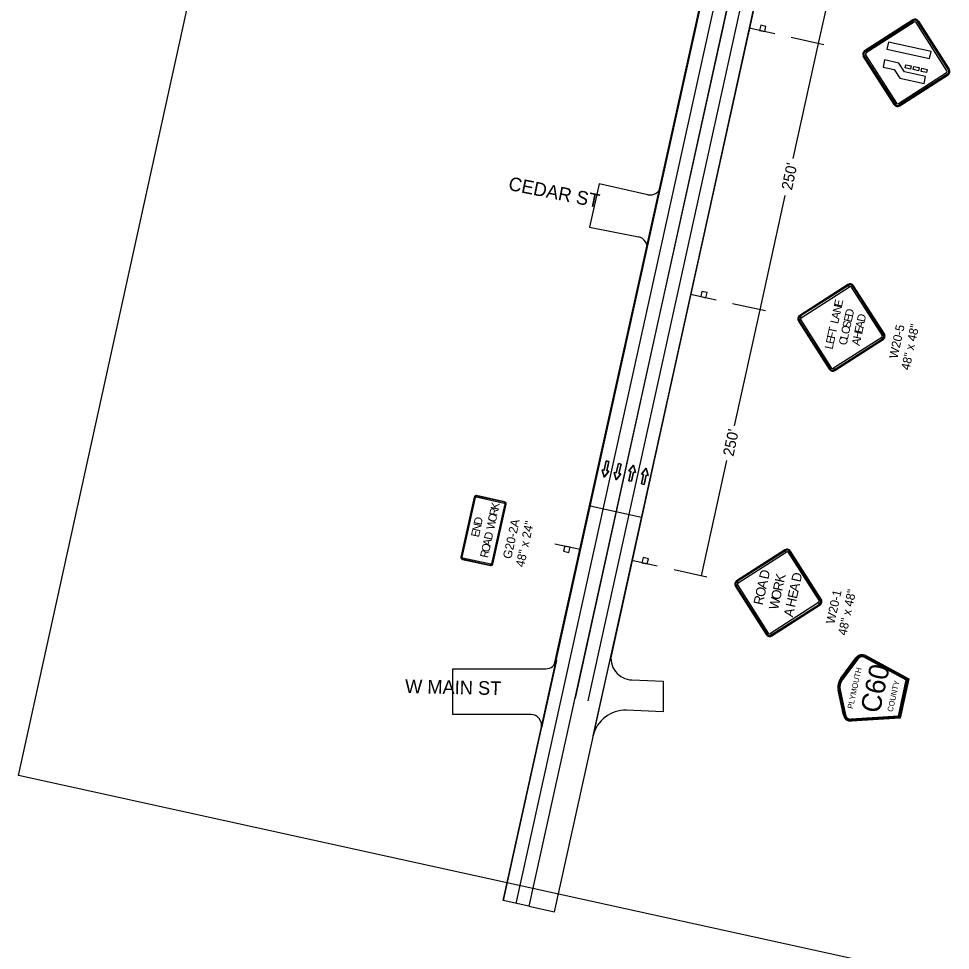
# Model space of a CAD drawing. Extents: x 14104283 to 14120882, y 8635219 to 8671666.
# Drawn here: x 14106925 to 14107780, y 8637146 to 8638001 of the extents above; entities that cross this region are included whole.
import ezdxf

# ---------------------------------------------------------------- set-up
doc = ezdxf.new("R2010")
doc.units = 0
for name, color, linetype in [('Cell', 7, 'Continuous'), ('Default', 7, 'Continuous'), ('dsnNonPlotable', 7, 'Continuous'), ('dsnPaintExistingBrokenLaneLineWhite', 7, 'Continuous'), ('dsnPaintExistingDoubleCenterYellow', 7, 'Continuous'), ('dsnPaintExistingEdgeLineRightWhite', 7, 'Continuous'), ('dsnStdLabel', 7, 'Continuous'), ('dsnTextOverlapOdd', 7, 'Continuous'), ('Sign', 7, 'Continuous')]:
    doc.layers.add(name, color=color, linetype=linetype)

msp = doc.modelspace()

# ---------------------------------------------------------------- linework, layer by layer
at = {"layer": 'Cell'}
for p, q in [((14107700.87, 8637971.42), (14107745.09, 8637999.71)), ((14107745.09, 8637999.71), (14107700.87, 8637971.42)), ((14107701.37, 8637970.63), (14107745.6, 8637998.92)), ((14107746.44, 8637997.61), (14107702.22, 8637969.31)), ((14107776.46, 8637953), (14107748.17, 8637997.23)), ((14107749.48, 8637998.07), (14107777.78, 8637953.84)), ((14107750.27, 8637998.57), (14107778.57, 8637954.35)), ((14107778.57, 8637954.35), (14107750.27, 8637998.57)), ((14107618.57, 8637986.78), (14107595.13, 8637991.93)), ((14107728.02, 8637922.01), (14107699.73, 8637966.24)), ((14107699.73, 8637966.24), (14107728.02, 8637922.01)), ((14107699.73, 8637966.24), (14107699.73, 8637966.24)), ((14107728.81, 8637922.52), (14107700.52, 8637966.74)), ((14107701.84, 8637967.58), (14107701.84, 8637967.59)), ((14107701.84, 8637967.58), (14107730.13, 8637923.36)), ((14107731.86, 8637922.98), (14107776.08, 8637951.28)), ((14107776.92, 8637949.96), (14107732.7, 8637921.67)), ((14107777.43, 8637949.17), (14107733.2, 8637920.88)), ((14107733.2, 8637920.88), (14107777.43, 8637949.17)), ((14107685.59, 8637756.92), (14107641.37, 8637728.63)), ((14107686.1, 8637756.13), (14107686.94, 8637754.82)), ((14107688.67, 8637754.44), (14107689.98, 8637755.28)), ((14107719.06, 8637711.56), (14107690.77, 8637755.78)), ((14107564.62, 8637742.67), (14107541.18, 8637747.82)), ((14107640.23, 8637723.45), (14107668.52, 8637679.22)), ((14107641.02, 8637723.95), (14107642.34, 8637724.8)), ((14107642.72, 8637726.52), (14107641.87, 8637727.84)), ((14107673.7, 8637678.09), (14107717.93, 8637706.38)), ((14107716.58, 8637708.49), (14107717.42, 8637707.17)), ((14107718.27, 8637711.05), (14107716.96, 8637710.21)), ((14107670.63, 8637680.57), (14107669.31, 8637679.73)), ((14107673.2, 8637678.88), (14107672.36, 8637680.19)), ((14107342.77, 8637561.94), (14107330.7, 8637507)), ((14107343.23, 8637561.84), (14107343.99, 8637561.68)), ((14107344.74, 8637562.15), (14107344.9, 8637562.92)), ((14107370.64, 8637557.74), (14107345, 8637563.37)), ((14107360, 8637500.57), (14107372.07, 8637555.51)), ((14107370.54, 8637557.28), (14107370.37, 8637556.52)), ((14107370.85, 8637555.78), (14107371.61, 8637555.61)), ((14107416.71, 8637519.21), (14107440.15, 8637514.06)), ((14107627.73, 8637513.57), (14107583.51, 8637485.28)), ((14107628.24, 8637512.78), (14107629.08, 8637511.46)), ((14107630.81, 8637511.09), (14107632.12, 8637511.93)), ((14107661.21, 8637468.21), (14107632.91, 8637512.43)), ((14107331.92, 8637506.74), (14107331.16, 8637506.9)), ((14107332.13, 8637504.77), (14107357.77, 8637499.14)), ((14107332.23, 8637505.23), (14107332.4, 8637505.99)), ((14107359.54, 8637500.67), (14107358.78, 8637500.84)), ((14107510.73, 8637498.55), (14107487.29, 8637503.7)), ((14107358.04, 8637500.36), (14107357.87, 8637499.6)), ((14107584.86, 8637483.17), (14107584.02, 8637484.49)), ((14107582.37, 8637480.1), (14107610.67, 8637435.87)), ((14107583.16, 8637480.6), (14107584.48, 8637481.44)), ((14107660.42, 8637467.7), (14107659.1, 8637466.86)), ((14107615.85, 8637434.73), (14107660.07, 8637463.03)), ((14107658.72, 8637465.13), (14107659.56, 8637463.82)), ((14107612.77, 8637437.22), (14107611.46, 8637436.38)), ((14107615.34, 8637435.53), (14107614.5, 8637436.84))]:
    msp.add_line(p, q, dxfattribs=at)
for points in [[(14107745.6, 8637998.92), (14107701.37, 8637970.63)], [(14107746.44, 8637997.61), (14107702.22, 8637969.31)], [(14107776.46, 8637953), (14107748.17, 8637997.23)], [(14107777.78, 8637953.84), (14107749.48, 8637998.07)], [(14107604.57, 8637989.94), (14107609.37, 8637988.89), (14107610.42, 8637993.68), (14107605.62, 8637994.74), (14107604.57, 8637989.94)], [(14107700.52, 8637966.74), (14107728.81, 8637922.52)], [(14107701.84, 8637967.59), (14107730.13, 8637923.36)], [(14107731.86, 8637922.98), (14107776.08, 8637951.28)], [(14107732.7, 8637921.67), (14107776.92, 8637949.96)], [(14107550.62, 8637745.83), (14107555.41, 8637744.78), (14107556.46, 8637749.57), (14107551.67, 8637750.63), (14107550.62, 8637745.83)], [(14107462.11, 8637586.65), (14107460.28, 8637587.05), (14107462, 8637580.28), (14107466.38, 8637585.72), (14107464.55, 8637586.12), (14107466.42, 8637594.67), (14107463.97, 8637595.2), (14107462.11, 8637586.65)], [(14107473.17, 8637584.22), (14107471.34, 8637584.62), (14107473.06, 8637577.85), (14107477.44, 8637583.29), (14107475.61, 8637583.69), (14107477.48, 8637592.24), (14107475.04, 8637592.77), (14107473.17, 8637584.22)], [(14107488.87, 8637584.97), (14107490.7, 8637584.57), (14107488.98, 8637591.35), (14107484.6, 8637585.91), (14107486.43, 8637585.51), (14107484.56, 8637576.96), (14107487.01, 8637576.43), (14107488.87, 8637584.97)], [(14107500.51, 8637582.16), (14107502.34, 8637581.76), (14107500.62, 8637588.53), (14107496.23, 8637583.09), (14107498.06, 8637582.69), (14107496.2, 8637574.14), (14107498.64, 8637573.61), (14107500.51, 8637582.16)], [(14107430.72, 8637516.05), (14107425.92, 8637517.1), (14107424.87, 8637512.3), (14107429.66, 8637511.25), (14107430.72, 8637516.05)], [(14107496.73, 8637501.71), (14107501.52, 8637500.66), (14107502.58, 8637505.45), (14107497.78, 8637506.51), (14107496.73, 8637501.71)]]:
    msp.add_lwpolyline(points, dxfattribs=at)
for points in [[(14107604.57, 8637989.94), (14107609.37, 8637988.89), (14107610.42, 8637993.68), (14107605.62, 8637994.74)], [(14107721.41, 8637972.77), (14107760.48, 8637964.18), (14107761.93, 8637970.78), (14107722.86, 8637979.36)], [(14107728.12, 8637954.01), (14107733.17, 8637946.12), (14107755.44, 8637941.23), (14107756.89, 8637947.82), (14107737.35, 8637952.11), (14107732.3, 8637960.01), (14107719.24, 8637962.88), (14107717.79, 8637956.28)], [(14107738.13, 8637955.65), (14107738.77, 8637958.58), (14107743.66, 8637957.51), (14107743.01, 8637954.58)], [(14107745.45, 8637954.04), (14107746.1, 8637956.97), (14107750.98, 8637955.9), (14107750.34, 8637952.97)], [(14107752.78, 8637952.44), (14107753.42, 8637955.37), (14107758.31, 8637954.29), (14107757.66, 8637951.36)], [(14107550.62, 8637745.83), (14107555.41, 8637744.78), (14107556.46, 8637749.57), (14107551.67, 8637750.63)], [(14107686.1, 8637756.13), (14107641.87, 8637727.84), (14107642.72, 8637726.52), (14107686.94, 8637754.82), (14107686.1, 8637756.13)], [(14107718.27, 8637711.05), (14107689.98, 8637755.28), (14107688.67, 8637754.44), (14107716.96, 8637710.21), (14107718.27, 8637711.05)], [(14107641.02, 8637723.95), (14107669.31, 8637679.73), (14107670.63, 8637680.57), (14107642.34, 8637724.8), (14107641.02, 8637723.95)], [(14107673.2, 8637678.88), (14107717.42, 8637707.17), (14107716.58, 8637708.49), (14107672.36, 8637680.19), (14107673.2, 8637678.88)], [(14107463.97, 8637595.2), (14107466.42, 8637594.67), (14107464.55, 8637586.12), (14107466.38, 8637585.72), (14107462, 8637580.28), (14107460.28, 8637587.05), (14107462.11, 8637586.65)], [(14107475.04, 8637592.77), (14107477.48, 8637592.24), (14107475.61, 8637583.69), (14107477.44, 8637583.29), (14107473.06, 8637577.85), (14107471.34, 8637584.62), (14107473.17, 8637584.22)], [(14107487.01, 8637576.43), (14107484.56, 8637576.96), (14107486.43, 8637585.51), (14107484.6, 8637585.91), (14107488.98, 8637591.35), (14107490.7, 8637584.57), (14107488.87, 8637584.97)], [(14107498.64, 8637573.61), (14107496.2, 8637574.14), (14107498.06, 8637582.69), (14107496.23, 8637583.09), (14107500.62, 8637588.53), (14107502.34, 8637581.76), (14107500.51, 8637582.16)], [(14107343.23, 8637561.84), (14107331.16, 8637506.9), (14107331.92, 8637506.74), (14107343.99, 8637561.68), (14107343.23, 8637561.84)], [(14107370.54, 8637557.28), (14107344.9, 8637562.92), (14107344.74, 8637562.15), (14107370.37, 8637556.52), (14107370.54, 8637557.28)], [(14107359.54, 8637500.67), (14107371.61, 8637555.61), (14107370.85, 8637555.78), (14107358.78, 8637500.84), (14107359.54, 8637500.67)], [(14107430.72, 8637516.05), (14107425.92, 8637517.1), (14107424.87, 8637512.3), (14107429.66, 8637511.25)], [(14107628.24, 8637512.78), (14107584.02, 8637484.49), (14107584.86, 8637483.17), (14107629.08, 8637511.46), (14107628.24, 8637512.78)], [(14107660.42, 8637467.7), (14107632.12, 8637511.93), (14107630.81, 8637511.09), (14107659.1, 8637466.86), (14107660.42, 8637467.7)], [(14107332.23, 8637505.23), (14107357.87, 8637499.6), (14107358.04, 8637500.36), (14107332.4, 8637505.99), (14107332.23, 8637505.23)], [(14107496.73, 8637501.71), (14107501.52, 8637500.66), (14107502.58, 8637505.45), (14107497.78, 8637506.51)], [(14107583.16, 8637480.6), (14107611.46, 8637436.38), (14107612.77, 8637437.22), (14107584.48, 8637481.44), (14107583.16, 8637480.6)], [(14107615.34, 8637435.53), (14107659.56, 8637463.82), (14107658.72, 8637465.13), (14107614.5, 8637436.84), (14107615.34, 8637435.53)]]:
    msp.add_lwpolyline(points, close=True, dxfattribs=at)
for centre, radius, start, end in [((14107747.11, 8637996.55), 3.75, 32.61026, 122.61047), ((14107747.11, 8637996.55), 3.75, 32.61026, 122.61047), ((14107747.11, 8637996.55), 2.81, 32.61026, 122.61047), ((14107747.11, 8637996.55), 2.81, 32.61026, 122.61047), ((14107747.11, 8637996.55), 1.25, 32.61026, 122.61047), ((14107747.11, 8637996.55), 1.25, 32.61026, 122.61047), ((14107702.89, 8637968.26), 3.75, 122.61047, 212.61022), ((14107702.89, 8637968.26), 3.75, 122.61047, 212.61022), ((14107702.89, 8637968.26), 2.81, 122.61047, 212.61022), ((14107702.89, 8637968.26), 2.81, 122.61047, 212.61022), ((14107702.89, 8637968.26), 1.25, 122.61047, 212.61022), ((14107702.89, 8637968.26), 1.25, 122.61047, 212.61022), ((14107775.41, 8637952.33), 2.81, 302.61005, 32.61026), ((14107775.41, 8637952.33), 2.81, 302.61005, 32.61026), ((14107775.41, 8637952.33), 3.75, 302.61005, 32.61026), ((14107775.41, 8637952.33), 3.75, 302.61005, 32.61026), ((14107775.41, 8637952.33), 1.25, 302.61005, 32.61026), ((14107775.41, 8637952.33), 1.25, 302.61005, 32.61026), ((14107731.18, 8637924.03), 3.75, 212.61041, 302.61005), ((14107731.18, 8637924.03), 3.75, 212.61041, 302.61005), ((14107731.18, 8637924.03), 2.81, 212.61041, 302.61005), ((14107731.18, 8637924.03), 2.81, 212.61041, 302.61005), ((14107731.18, 8637924.03), 1.25, 212.61041, 302.61005), ((14107731.18, 8637924.03), 1.25, 212.61041, 302.61005), ((14107687.61, 8637753.76), 3.75, 32.61038, 122.61001), ((14107687.61, 8637753.76), 2.81, 32.61038, 122.61001), ((14107687.61, 8637753.76), 1.25, 32.61038, 122.61001), ((14107643.39, 8637725.47), 3.75, 122.6102, 212.60995), ((14107643.39, 8637725.47), 2.81, 122.6102, 212.60995), ((14107643.39, 8637725.47), 1.25, 122.6102, 212.60995), ((14107715.91, 8637709.54), 1.25, 302.61016, 32.61038), ((14107715.91, 8637709.54), 2.81, 302.61016, 32.61038), ((14107715.91, 8637709.54), 3.75, 302.61016, 32.61038), ((14107671.68, 8637681.25), 1.25, 212.60995, 302.61016), ((14107671.68, 8637681.25), 3.75, 212.60995, 302.61016), ((14107671.68, 8637681.25), 2.81, 212.60995, 302.61016), ((14107344.6, 8637561.54), 1.87, 77.61021, 167.61042), ((14107344.6, 8637561.54), 1.41, 77.61021, 167.61042), ((14107344.6, 8637561.54), 0.625, 77.61021, 167.61042), ((14107370.24, 8637555.91), 0.625, 347.61027, 77.61048), ((14107370.24, 8637555.91), 1.41, 347.61027, 77.61048), ((14107370.24, 8637555.91), 1.87, 347.61027, 77.61048), ((14107629.75, 8637510.41), 3.75, 32.61038, 122.61001), ((14107629.75, 8637510.41), 2.81, 32.61038, 122.61001), ((14107629.75, 8637510.41), 1.25, 32.61038, 122.61001), ((14107332.53, 8637506.6), 1.87, 167.61042, 257.61006), ((14107332.53, 8637506.6), 1.41, 167.61042, 257.61006), ((14107332.53, 8637506.6), 0.625, 167.61042, 257.61006), ((14107358.17, 8637500.97), 0.625, 257.61006, 347.61027), ((14107358.17, 8637500.97), 1.87, 257.61006, 347.61027), ((14107358.17, 8637500.97), 1.41, 257.61006, 347.61027), ((14107585.53, 8637482.12), 3.75, 122.6102, 212.60995), ((14107585.53, 8637482.12), 2.81, 122.6102, 212.60995), ((14107585.53, 8637482.12), 1.25, 122.6102, 212.60995), ((14107658.05, 8637466.19), 1.25, 302.61016, 32.61038), ((14107658.05, 8637466.19), 2.81, 302.61016, 32.61038), ((14107658.05, 8637466.19), 3.75, 302.61016, 32.61038), ((14107613.82, 8637437.89), 3.75, 212.60995, 302.61016), ((14107613.82, 8637437.89), 2.81, 212.60995, 302.61016), ((14107613.82, 8637437.89), 1.25, 212.60995, 302.61016)]:
    msp.add_arc(centre, radius, start, end, dxfattribs=at)
at = {"layer": 'Default'}
for p, q in [((14107457.32, 8637849.19), (14107448.62, 8637809.68)), ((14107502.22, 8637839.3), (14107457.32, 8637849.19)), ((14107501.26, 8637788.6), (14107514.14, 8637846.91)), ((14107448.62, 8637809.68), (14107493.49, 8637800.56)), ((14107451.98, 8637342.9), (14107468.68, 8637418.51)), ((14107418.16, 8637412.31), (14107404.47, 8637350.31)), ((14107323.16, 8637404.47), (14107408.39, 8637404.47)), ((14107323.16, 8637362.47), (14107323.16, 8637404.47)), ((14107487.45, 8637394.21), (14107516.02, 8637393.12)), ((14107516.02, 8637393.12), (14107516.02, 8637365.12)), ((14107516.02, 8637365.12), (14107482.42, 8637366.4)), ((14107394.7, 8637362.47), (14107323.16, 8637362.47))]:
    msp.add_line(p, q, dxfattribs=at)
for points in [[(14107392.92, 8637186.73), (14107369.48, 8637191.91), (14107655.09, 8638485.14), (14107678.52, 8638479.96)], [(14107602.34, 8638246.31), (14107649.23, 8638236.01), (14107496.22, 8637543.21), (14107449.34, 8637553.51)], [(14107416.35, 8637181.55), (14107649.12, 8638235.55), (14107625.69, 8638240.73), (14107392.92, 8637186.73)]]:
    msp.add_lwpolyline(points, close=True, dxfattribs=at)
for centre, radius, start, end in [((14107504.37, 8637849.06), 10, 257.58106, 347.54626), ((14107491.49, 8637790.76), 10, 347.54626, 78.50271), ((14107488.21, 8637414.2), 20, 167.54626, 267.81775), ((14107408.39, 8637414.47), 10, 270, 347.54626), ((14107481.28, 8637336.43), 30, 87.81775, 167.54626), ((14107394.7, 8637352.47), 10, 347.54626, 90)]:
    msp.add_arc(centre, radius, start, end, dxfattribs=at)
at = {"layer": 'dsnNonPlotable'}
msp.add_lwpolyline([(14106924.98, 8637306.69), (14107261.36, 8638837.67), (14108247.83, 8638620.92), (14107911.44, 8637089.94)], close=True, dxfattribs=at)
at = {"layer": 'dsnPaintExistingBrokenLaneLineWhite'}
for p, q in [((14107381.2, 8637189.32), (14107721.79, 8638731.54)), ((14107447.5, 8637375.04), (14107637.12, 8638238.2))]:
    msp.add_line(p, q, dxfattribs=at)
at = {"layer": 'dsnPaintExistingDoubleCenterYellow'}
msp.add_line((14107435.78, 8637377.61), (14107677.97, 8638480.08), dxfattribs=at)
at = {"layer": 'dsnPaintExistingEdgeLineRightWhite'}
for p, q in [((14107468.79, 8637415.99), (14107828.52, 8639053.57)), ((14107708.89, 8638734.37), (14107415.88, 8637407.61)), ((14107406.84, 8637361.06), (14107369.48, 8637191.91))]:
    msp.add_line(p, q, dxfattribs=at)
at = {"layer": 'dsnStdLabel'}
for p, q in [((14107658.66, 8637977.98), (14107681.84, 8638083.5)), ((14107663.54, 8637976.9), (14107633.43, 8637983.52)), ((14107635.5, 8637872.53), (14107658.66, 8637977.98)), ((14107605.02, 8637733.8), (14107628.07, 8637838.73)), ((14107609.9, 8637732.72), (14107579.79, 8637739.34)), ((14107581.6, 8637627.19), (14107605.02, 8637733.8)), ((14107551.38, 8637489.62), (14107574.63, 8637595.47)), ((14107556.26, 8637488.55), (14107526.15, 8637495.16))]:
    msp.add_line(p, q, dxfattribs=at)
at = {"layer": 'Sign'}
for p, q in [((14107740.26, 8637394.71), (14107701.44, 8637415.71)), ((14107701.44, 8637415.71), (14107740.26, 8637394.71)), ((14107701.9, 8637416.57), (14107741.36, 8637395.22)), ((14107679.05, 8637395.78), (14107692.99, 8637414.59)), ((14107693.77, 8637414.01), (14107679.84, 8637395.2)), ((14107679.84, 8637395.2), (14107693.77, 8637414.01)), ((14107680.62, 8637394.62), (14107694.55, 8637413.43)), ((14107694.55, 8637413.43), (14107680.62, 8637394.62)), ((14107700.98, 8637414.86), (14107739.15, 8637394.21)), ((14107739.15, 8637394.21), (14107700.98, 8637414.86)), ((14107739.15, 8637394.21), (14107731.93, 8637361.14)), ((14107731.93, 8637361.14), (14107739.15, 8637394.21)), ((14107732.73, 8637360.21), (14107740.26, 8637394.71)), ((14107740.26, 8637394.71), (14107732.73, 8637360.21)), ((14107741.36, 8637395.22), (14107733.52, 8637359.29)), ((14107741.36, 8637395.22), (14107740.26, 8637394.71)), ((14107681.48, 8637361.84), (14107676.64, 8637384.74)), ((14107677.6, 8637384.94), (14107682.43, 8637362.04)), ((14107682.43, 8637362.04), (14107677.6, 8637384.94)), ((14107683.38, 8637362.24), (14107678.55, 8637385.14)), ((14107678.55, 8637385.14), (14107683.38, 8637362.24)), ((14107731.93, 8637361.14), (14107688.63, 8637358.26)), ((14107688.63, 8637358.26), (14107731.93, 8637361.14)), ((14107688.69, 8637357.29), (14107732.73, 8637360.21)), ((14107732.73, 8637360.21), (14107688.69, 8637357.29)), ((14107733.52, 8637359.29), (14107688.76, 8637356.32)), ((14107731.93, 8637361.14), (14107732.73, 8637360.21))]:
    msp.add_line(p, q, dxfattribs=at)
for centre, radius, start, end in [((14107698.59, 8637410.44), 6.97, 61.58827, 143.46107), ((14107698.59, 8637410.44), 5.99, 61.58827, 143.46107), ((14107698.59, 8637410.44), 5.99, 61.58827, 143.46107), ((14107698.59, 8637410.44), 5.02, 61.58827, 143.46107), ((14107698.59, 8637410.44), 5.02, 61.58827, 143.46107), ((14107690.12, 8637387.58), 13.77, 143.46107, 191.92127), ((14107690.12, 8637387.58), 12.8, 143.46107, 191.92127), ((14107690.12, 8637387.58), 12.8, 143.46107, 191.92127), ((14107690.12, 8637387.58), 11.83, 143.46107, 191.92127), ((14107690.12, 8637387.58), 11.83, 143.46107, 191.92127), ((14107688.3, 8637363.27), 6.97, 191.92127, 273.79407), ((14107688.3, 8637363.27), 5.99, 191.92127, 273.79407), ((14107688.3, 8637363.27), 5.99, 191.92127, 273.79407), ((14107688.3, 8637363.27), 5.02, 191.92127, 273.79407), ((14107688.3, 8637363.27), 5.02, 191.92127, 273.79407)]:
    msp.add_arc(centre, radius, start, end, dxfattribs=at)

# ---------------------------------------------------------------- texts
at = {"layer": 'Cell'}
for s, height, p in [('E', 7.5, (14107680.01, 8637735.91)), ('N', 7.5, (14107678.79, 8637730.36)), ('D', 7.5, (14107690.01, 8637726.79)), ('L', 7.5, (14107676.62, 8637720.47)), ('A', 7.5, (14107677.51, 8637724.54)), ('S', 7.5, (14107687.71, 8637716.34)), ('E', 7.5, (14107688.93, 8637721.89)), ('D', 7.5, (14107700.96, 8637722.05)), ('T', 7.5, (14107674.6, 8637711.27)), ('O', 7.5, (14107686.51, 8637710.87)), ('E', 7.5, (14107698.7, 8637711.77)), ('A', 7.5, (14107699.69, 8637716.25)), ('W20-5', 8, (14107730.97, 8637688.41)), ('48" x 48"', 8, (14107741.99, 8637677.98)), ('E', 7.5, (14107672.54, 8637701.88)), ('F', 7.5, (14107673.61, 8637706.78)), ('C', 7.5, (14107684.28, 8637700.73)), ('L', 7.5, (14107685.43, 8637705.97)), ('A', 7.5, (14107696.21, 8637700.43)), ('H', 7.5, (14107697.49, 8637706.23)), ('L', 7.5, (14107671.46, 8637696.98)), ('K', 7.5, (14107365.03, 8637549.66)), ('D', 7.5, (14107349.5, 8637535.78)), ('O', 7.5, (14107362.55, 8637538.4)), ('R', 7.5, (14107363.82, 8637544.15)), ('N', 7.5, (14107348.2, 8637529.88)), ('W', 7.5, (14107361.08, 8637531.69)), ('G20-2A', 8, (14107376.79, 8637504.77)), ('48" x 24"', 8, (14107388.46, 8637497.29)), ('E', 7.5, (14107347.06, 8637524.69)), ('D', 7.5, (14107358.99, 8637522.19)), ('O', 7.5, (14107356.52, 8637510.95)), ('A', 7.5, (14107357.72, 8637516.4)), ('R', 7.5, (14107355.38, 8637505.74)), ('D', 8.75, (14107612.56, 8637486.05)), ('D', 8.75, (14107642.08, 8637483.5)), ('A', 8.75, (14107610.65, 8637477.32)), ('R', 8.75, (14107625.22, 8637475.22)), ('K', 8.75, (14107626.92, 8637482.96)), ('O', 8.75, (14107608.98, 8637469.72)), ('O', 8.75, (14107623.46, 8637467.21)), ('E', 8.75, (14107638.73, 8637468.24)), ('A', 8.75, (14107640.13, 8637474.61)), ('W20-1', 8, (14107673.12, 8637445.09)), ('48" x 48"', 8, (14107684.13, 8637434.63)), ('R', 8.75, (14107607.37, 8637462.39)), ('W', 8.75, (14107621.47, 8637458.12)), ('H', 8.75, (14107636.99, 8637460.31)), ('A', 8.75, (14107635.03, 8637451.42))]:
    msp.add_text(s, height=height, rotation=77.61021, dxfattribs=at).set_placement(p)
at = {"layer": 'dsnStdLabel'}
for p in [(14107634.21, 8637842.93), (14107580.57, 8637598.76)]:
    msp.add_text("250'", height=10, rotation=78.05307, dxfattribs=at).set_placement(p)
at = {"layer": 'dsnTextOverlapOdd'}
for s, rotation, p in [('CEDAR ST', 348.69117, (14107373.5, 8637843.78)), ('W MAIN ST', 358.69117, (14107279.34, 8637382.3))]:
    msp.add_text(s, height=12.5, rotation=rotation, dxfattribs=at).set_placement(p)
at = {"layer": 'Sign'}
for s, height, p in [('C60', 18.144, (14107714.57, 8637362.83)), ('PLYMOUTH', 5.184, (14107690.12, 8637367.4)), ('COUNTY', 5.184, (14107726.7, 8637364.63))]:
    msp.add_text(s, height=height, rotation=77.69117, dxfattribs=at).set_placement(p)

doc.saveas('drawing.dxf')
